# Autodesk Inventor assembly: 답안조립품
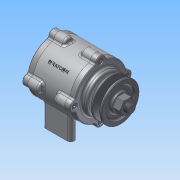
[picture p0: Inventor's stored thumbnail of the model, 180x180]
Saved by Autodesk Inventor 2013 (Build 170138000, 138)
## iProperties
Created: 2015-03
Part Number: 답안조립품
Document SubType Name: Assembly
Designer: Administrator
Author: Administrator
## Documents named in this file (11)
- C:\Users\Administrator\Desktop\450306V1035\답안조립품.iam
- C:\Users\Administrator\Desktop\450306V1035\본체.ipt
- C:\Users\Administrator\Desktop\450306V1035\축.ipt
- C:\Users\Administrator\Desktop\450306V1035\키(4 x 4 x 12).ipt
- C:\Users\Administrator\Desktop\450306V1035\베어링 6204.ipt
- C:\Users\Administrator\Desktop\450306V1035\커버.ipt
- C:\Users\Administrator\Desktop\450306V1035\커버2.ipt
- C:\Users\Administrator\Desktop\450306V1035\오일실.ipt
- C:\Users\Administrator\Desktop\450306V1035\M 4 x 12.ipt
- C:\Users\Administrator\Desktop\450306V1035\V벨트풀리.ipt
- C:\Users\Administrator\Desktop\450306V1035\너트 M12x1.25.ipt
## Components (14 placed, 6 different names)
1. KS B 1311 (I) 4 x 4 x 12:1
2. KS B 2023 6204 - 20 x 47 x 14:1
3. KS B 2023 6204 - 20 x 47 x 14:2
4. KS B 2804 D D - 20 32 8:1
5. 그루브 풀리1:1
6. KS B 1012 클래스 1 일반 - 미터 M12x1.25:1
7. KS B 1003 - 미터 M 4 x 12:1
8. KS B 1003 - 미터 M 4 x 12:3
9. KS B 1003 - 미터 M 4 x 12:4
10. KS B 1003 - 미터 M 4 x 12:5
11. KS B 1003 - 미터 M 4 x 12:2
12. KS B 1003 - 미터 M 4 x 12:6
13. KS B 1003 - 미터 M 4 x 12:7
14. KS B 1003 - 미터 M 4 x 12:8
